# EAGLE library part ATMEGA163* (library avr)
MICROCONTROLLER 16 Kbytes FLASH, 1 Kbytes EEPROM 1 Kbytes SRAM UART 8-channel 10 bit ADC hardware multiplier
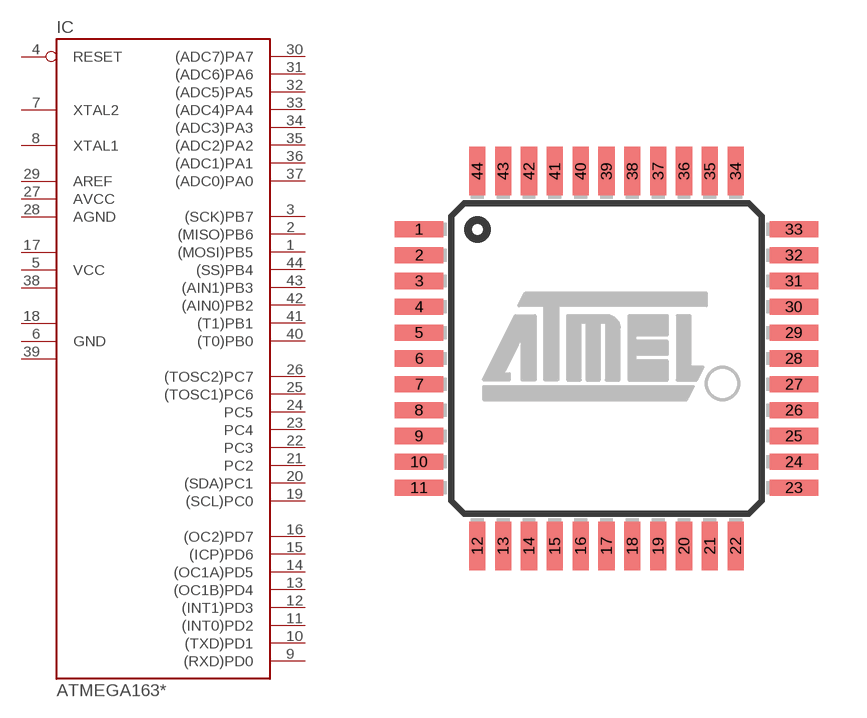
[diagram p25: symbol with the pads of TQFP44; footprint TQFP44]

Designator prefix IC

## ATMEGA163-8A, ATMEGA163L-4A  [TQFP44]
1  (MOSI)PB5
2  (MISO)PB6
3  (SCK)PB7
4  RESET  in
5  VCC  pwr
6  GND  pwr
7  XTAL2
8  XTAL1
9  (RXD)PD0
10  (TXD)PD1
11  (INT0)PD2
12  (INT1)PD3
13  (OC1B)PD4
14  (OC1A)PD5
15  (ICP)PD6
16  (OC2)PD7
17  VCC1  pwr
18  GND1  pwr
19  (SCL)PC0
20  (SDA)PC1
21  PC2
22  PC3
23  PC4
24  PC5
25  (TOSC1)PC6
26  (TOSC2)PC7
27  AVCC  pwr
28  AGND  pwr
29  AREF  pwr
30  (ADC7)PA7
31  (ADC6)PA6
32  (ADC5)PA5
33  (ADC4)PA4
34  (ADC3)PA3
35  (ADC2)PA2
36  (ADC1)PA1
37  (ADC0)PA0
38  VCC2  pwr
39  GND2  pwr
40  (T0)PB0
41  (T1)PB1
42  (AIN0)PB2
43  (AIN1)PB3
44  (SS)PB4

## Footprint TQFP44 (pad centres in mm)
Thin Plasic Quad Flat Package
smd 1.5 x 0.5: 1 -5.8,4; 2 -5.8,3.2; 3 -5.8,2.4; 4 -5.8,1.6; 5 -5.8,0.8; 6 -5.8,0; 7 -5.8,-0.8; 8 -5.8,-1.6; 9 -5.8,-2.4; 10 -5.8,-3.2; 11 -5.8,-4; 23 5.8,-4; 24 5.8,-3.2; 25 5.8,-2.4; 26 5.8,-1.6; 27 5.8,-0.8; 28 5.8,0; 29 5.8,0.8; 30 5.8,1.6; 31 5.8,2.4; 32 5.8,3.2; 33 5.8,4
smd 0.5 x 1.5: 12 -4,-5.8; 13 -3.2,-5.8; 14 -2.4,-5.8; 15 -1.6,-5.8; 16 -0.8,-5.8; 17 0,-5.8; 18 0.8,-5.8; 19 1.6,-5.8; 20 2.4,-5.8; 21 3.2,-5.8; 22 4,-5.8; 34 4,5.8; 35 3.2,5.8; 36 2.4,5.8; 37 1.6,5.8; 38 0.8,5.8; 39 0,5.8; 40 -0.8,5.8; 41 -1.6,5.8; 42 -2.4,5.8; 43 -3.2,5.8; 44 -4,5.8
